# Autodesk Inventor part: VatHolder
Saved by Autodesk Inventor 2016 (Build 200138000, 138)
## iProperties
Created: 2016-01
Part Number: VatHolder
Material: Generic
Document SubType Name: Modeling
Designer: John
Density: 1 g/cm^3
Appearance: Default
Author: John
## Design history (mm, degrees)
feature "SOLID1"
body "Solid1"
